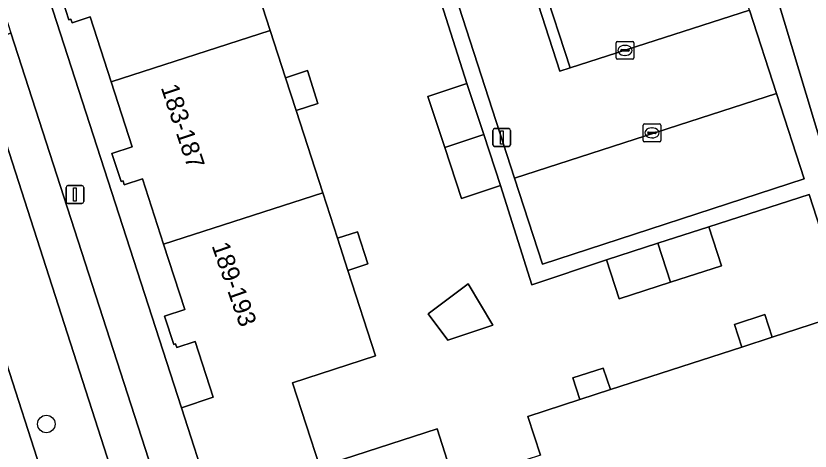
# Model space of a CAD drawing. Extents: x 159371 to 159986, y 382987 to 383597.
# Drawn here: x 159505.97 to 159550.53, y 383040.59 to 383065.02 of the extents above; entities that cross this region are included whole.
import ezdxf

# ---------------------------------------------------------------- set-up
doc = ezdxf.new("R2010")
doc.units = 0
for name, color, linetype in [('IMGEO_Boom', 7, 'Continuous'), ('IMGEO_Erf', 7, 'Continuous'), ('IMGEO_Fietspad_open', 7, 'Continuous'), ('IMGEO_Groenvoorziening', 7, 'Continuous'), ('IMGEO_Kolk', 7, 'Continuous'), ('IMGEO_Lichtmast', 7, 'Continuous'), ('IMGEO_Muur', 7, 'Continuous'), ('IMGEO_Pand', 7, 'Continuous'), ('IMGEO_Pand_nummerreeks', 7, 'Continuous'), ('IMGEO_Parkeervlak_open', 7, 'Continuous'), ('IMGEO_Rijbaan_lokaal_open', 7, 'Continuous'), ('IMGEO_Voetpad_open', 7, 'Continuous')]:
    doc.layers.add(name, color=color, linetype=linetype)

msp = doc.modelspace()

# ---------------------------------------------------------------- linework, layer by layer
at = {"layer": 'IMGEO_Boom'}
msp.add_circle((159507.682, 383042.11), 0.489, dxfattribs=at)
at = {"layer": 'IMGEO_Erf'}
for points in [[(159590.076, 383081.989), (159589.756, 383082.472), (159584.535, 383080.817), (159583.508, 383080.491), (159581.119, 383079.733), (159581.591, 383078.278), (159548.258, 383067.467), (159552.839, 383052.245), (159554.73, 383049.152), (159594.612, 383075.126)], [(159531.349, 383049.982), (159532.738, 383047.665), (159530.204, 383046.821), (159529.093, 383048.294)]]:
    msp.add_lwpolyline(points, close=True, dxfattribs=at)
for points in [[(159551.523, 383051.759), (159550.477, 383054.997), (159544.852, 383053.181), (159545.561, 383050.993), (159542.692, 383050.064), (159539.824, 383049.134), (159539.114, 383051.321), (159534.921, 383049.93), (159533.162, 383055.495), (159530.977, 383054.774), (159530.033, 383057.637), (159529.089, 383060.5), (159531.273, 383061.22), (159527.278, 383073.835)], [(159518.756, 383068.777), (159520.239, 383064.195), (159521.097, 383061.545), (159522.324, 383061.942), (159522.921, 383060.1), (159521.694, 383059.702), (159523.189, 383055.084), (159524.013, 383052.538), (159525.129, 383052.899), (159525.712, 383051.095), (159524.597, 383050.734), (159526.147, 383045.944), (159521.484, 383044.429), (159523.019, 383039.702), (159529.6, 383041.839), (159530.588, 383038.795)], [(159535.4, 383040.357), (159534.692, 383042.535), (159537.609, 383043.482), (159537.215, 383044.697), (159538.927, 383045.253), (159539.322, 383044.039), (159546.693, 383046.432), (159546.283, 383047.695), (159547.99, 383048.249), (159548.4, 383046.987), (159553.469, 383048.633)]]:
    msp.add_lwpolyline(points, dxfattribs=at)
at = {"layer": 'IMGEO_Fietspad_open'}
msp.add_arc((159691.276, 383107.789), 197.962, 197.58879, 201.43204, dxfattribs=at)
at = {"layer": 'IMGEO_Groenvoorziening'}
msp.add_lwpolyline([(159505.691, 383064.068), (159504.66, 383063.593), (159505.38, 383061.288), (159504.908, 383059.446), (159515.199, 383027.456), (159517.392, 383027.837)], close=True, dxfattribs=at)
for points in [[(159510.486, 383031.236), (159512.634, 383027.01), (159515.199, 383027.456), (159504.908, 383059.446), (159505.38, 383061.288), (159504.66, 383063.593), (159505.691, 383064.068)], [(159502.496, 383054.651), (159508.715, 383035.357)]]:
    msp.add_lwpolyline(points, dxfattribs=at)
at = {"layer": 'IMGEO_Kolk'}
for p, q in [((159539.642, 383062.653), (159539.642, 383063.505)), ((159539.717, 383063.579), (159540.569, 383063.579)), ((159540.643, 383063.505), (159540.643, 383062.653)), ((159539.901, 383063.073), (159539.901, 383063.085)), ((159540.339, 383063.036), (159539.941, 383063.036)), ((159539.944, 383063.122), (159540.342, 383063.122)), ((159540.13, 383063.359), (159540.155, 383063.359)), ((159540.385, 383063.085), (159540.385, 383063.073)), ((159540.569, 383062.579), (159539.717, 383062.579)), ((159540.153, 383062.799), (159540.128, 383062.799)), ((159541.155, 383058.025), (159541.155, 383058.877)), ((159541.23, 383058.951), (159542.082, 383058.951)), ((159541.643, 383058.731), (159541.668, 383058.731)), ((159542.156, 383058.877), (159542.156, 383058.025)), ((159541.414, 383058.445), (159541.414, 383058.457)), ((159541.852, 383058.408), (159541.454, 383058.408)), ((159541.457, 383058.494), (159541.855, 383058.494)), ((159541.666, 383058.171), (159541.641, 383058.171)), ((159541.898, 383058.457), (159541.898, 383058.445)), ((159542.082, 383057.951), (159541.23, 383057.951))]:
    msp.add_line(p, q, dxfattribs=at)
for points in [[(159539.642, 383062.653), (159539.642, 383063.505)], [(159539.717, 383063.579), (159540.569, 383063.579)], [(159540.643, 383063.505), (159540.643, 383062.653)], [(159540.569, 383062.579), (159539.717, 383062.579)], [(159541.155, 383058.025), (159541.155, 383058.877)], [(159541.23, 383058.951), (159542.082, 383058.951)], [(159542.156, 383058.877), (159542.156, 383058.025)], [(159542.082, 383057.951), (159541.23, 383057.951)]]:
    msp.add_lwpolyline(points, dxfattribs=at)
for centre, radius, start, end in [((159539.719, 383063.503), 0.0765, 91.552, 178.448), ((159539.719, 383063.503), 0.0765, 91.552, 178.448), ((159540.567, 383063.503), 0.0765, 1.552, 88.448), ((159540.567, 383063.503), 0.0765, 1.552, 88.448), ((159539.941, 383063.082), 0.0403, 85.8775, 175.7526), ((159539.938, 383063.072), 0.0366, 178.938, 274.7102), ((159540.342, 383063.079), 0.043, 264.8664, 352.4533), ((159540.346, 383063.084), 0.0386, 1.7309, 96.639), ((159539.719, 383062.655), 0.0765, 181.552, 268.448), ((159539.719, 383062.655), 0.0765, 181.552, 268.448), ((159540.567, 383062.655), 0.0765, 271.552, 358.448), ((159540.567, 383062.655), 0.0765, 271.552, 358.448), ((159541.232, 383058.875), 0.0765, 91.552, 178.448), ((159541.232, 383058.875), 0.0765, 91.552, 178.448), ((159542.08, 383058.875), 0.0765, 1.552, 88.448), ((159542.08, 383058.875), 0.0765, 1.552, 88.448), ((159541.454, 383058.454), 0.0403, 85.8775, 175.7526), ((159541.451, 383058.444), 0.0366, 178.938, 274.7102), ((159541.855, 383058.451), 0.043, 264.8664, 352.4533), ((159541.859, 383058.456), 0.0386, 1.7309, 96.639), ((159541.232, 383058.027), 0.0765, 181.552, 268.448), ((159541.232, 383058.027), 0.0765, 181.552, 268.448), ((159542.08, 383058.027), 0.0765, 271.552, 358.448), ((159542.08, 383058.027), 0.0765, 271.552, 358.448)]:
    msp.add_arc(centre, radius, start, end, dxfattribs=at)
for centre, major_axis, ratio, start_param, end_param in [((159540.129, 383063.079), (-0.387, 0.002), 0.722429, 4.712389, 7.853982), ((159540.154, 383063.079), (-0.39, 0.002), 0.717154, 1.570796, 4.712389), ((159541.642, 383058.451), (-0.387, 0.002), 0.722429, 4.712389, 7.853982), ((159541.667, 383058.451), (-0.39, 0.002), 0.717154, 1.570796, 4.712389)]:
    msp.add_ellipse(centre, major_axis=major_axis, ratio=ratio, start_param=start_param, end_param=end_param, dxfattribs=at)
at = {"layer": 'IMGEO_Lichtmast'}
for p, q in [((159532.731, 383057.787), (159532.731, 383058.587)), ((159532.731, 383058.587), (159532.731, 383057.787)), ((159532.831, 383058.687), (159533.621, 383058.687)), ((159533.621, 383058.687), (159532.831, 383058.687)), ((159533.721, 383058.587), (159533.721, 383057.787)), ((159533.721, 383057.787), (159533.721, 383058.587)), ((159533.621, 383057.687), (159532.831, 383057.687)), ((159532.831, 383057.687), (159533.621, 383057.687)), ((159508.886, 383055.491), (159509.676, 383055.491)), ((159509.676, 383055.491), (159508.886, 383055.491)), ((159508.786, 383054.591), (159508.786, 383055.391)), ((159508.786, 383055.391), (159508.786, 383054.591)), ((159509.776, 383055.391), (159509.776, 383054.591)), ((159509.776, 383054.591), (159509.776, 383055.391)), ((159509.676, 383054.491), (159508.886, 383054.491)), ((159508.886, 383054.491), (159509.676, 383054.491))]:
    msp.add_line(p, q, dxfattribs=at)
for points in [[(159533.151, 383058.562), (159533.301, 383058.562), (159533.301, 383057.812), (159533.151, 383057.812), (159533.151, 383058.562)], [(159509.206, 383055.366), (159509.356, 383055.366), (159509.356, 383054.616), (159509.206, 383054.616), (159509.206, 383055.366)]]:
    msp.add_lwpolyline(points, dxfattribs=at)
for centre, start, end in [((159532.831, 383058.587), 90, 180), ((159532.831, 383058.587), 90, 180), ((159533.621, 383058.587), 0, 90), ((159533.621, 383058.587), 360, 90), ((159532.831, 383057.787), 180, 270), ((159532.831, 383057.787), 180, 270), ((159533.621, 383057.787), 270, 0), ((159533.621, 383057.787), 270, 0), ((159508.886, 383055.391), 90, 180), ((159508.886, 383055.391), 90, 180), ((159509.676, 383055.391), 0, 90), ((159509.676, 383055.391), 360, 90), ((159508.886, 383054.591), 180, 270), ((159508.886, 383054.591), 180, 270), ((159509.676, 383054.591), 270, 0), ((159509.676, 383054.591), 270, 0)]:
    msp.add_arc(centre, 0.1, start, end, dxfattribs=at)
at = {"layer": 'IMGEO_Muur'}
for points in [[(159527.278, 383073.835), (159531.273, 383061.22)], [(159539.114, 383051.321), (159534.921, 383049.93), (159533.162, 383055.495)], [(159544.852, 383053.181), (159550.477, 383054.997)]]:
    msp.add_lwpolyline(points, dxfattribs=at)
at = {"layer": 'IMGEO_Pand'}
for points in [[(159518.756, 383068.777), (159518.086, 383070.848), (159517.273, 383073.361), (159508.363, 383070.484), (159509.565, 383066.759), (159508.431, 383066.382), (159508.949, 383064.802), (159509.054, 383064.837), (159509.123, 383064.628), (159510.145, 383064.963), (159511.322, 383061.317), (159520.239, 383064.195)], [(159521.694, 383059.702), (159521.097, 383061.545), (159520.239, 383064.195), (159511.322, 383061.317), (159512.498, 383057.672), (159511.364, 383057.295), (159511.882, 383055.715), (159511.987, 383055.75), (159512.056, 383055.541), (159513.078, 383055.876), (159514.262, 383052.204), (159523.189, 383055.084)], [(159521.097, 383061.545), (159521.694, 383059.702), (159522.921, 383060.1), (159522.324, 383061.942)], [(159530.033, 383057.637), (159532.218, 383058.358), (159531.273, 383061.22), (159529.089, 383060.5)], [(159530.033, 383057.637), (159530.977, 383054.774), (159533.162, 383055.495), (159532.218, 383058.358)], [(159521.484, 383044.429), (159526.147, 383045.944), (159524.597, 383050.734), (159524.013, 383052.538), (159523.189, 383055.084), (159514.262, 383052.204), (159515.447, 383048.532), (159514.313, 383048.155), (159514.831, 383046.575), (159514.936, 383046.61), (159515.005, 383046.401), (159516.028, 383046.736), (159517.034, 383043.617), (159515.265, 383043.021), (159518.438, 383033.149), (159522.589, 383034.496), (159524.454, 383035.101), (159523.976, 383036.575), (159523.019, 383039.702)], [(159542.692, 383050.064), (159545.561, 383050.993), (159544.852, 383053.181), (159541.983, 383052.251)], [(159524.013, 383052.538), (159524.597, 383050.734), (159525.712, 383051.095), (159525.129, 383052.899)], [(159542.692, 383050.064), (159541.983, 383052.251), (159539.114, 383051.321), (159539.824, 383049.134)], [(159529.093, 383048.294), (159530.204, 383046.821), (159532.738, 383047.665), (159531.349, 383049.982)], [(159556.336, 383044.392), (159554.984, 383043.971), (159553.469, 383048.633), (159548.4, 383046.987), (159546.693, 383046.432), (159539.322, 383044.039), (159537.609, 383043.482), (159534.692, 383042.535), (159535.4, 383040.357), (159530.588, 383038.795), (159529.6, 383041.839), (159523.019, 383039.702), (159523.976, 383036.575), (159526.049, 383037.247), (159526.758, 383035.059), (159525.407, 383034.621), (159526.629, 383030.733), (159557.552, 383040.764)], [(159546.693, 383046.432), (159548.4, 383046.987), (159547.99, 383048.249), (159546.283, 383047.695)], [(159537.609, 383043.482), (159539.322, 383044.039), (159538.927, 383045.253), (159537.215, 383044.697)]]:
    msp.add_lwpolyline(points, close=True, dxfattribs=at)
at = {"layer": 'IMGEO_Parkeervlak_open'}
for points in [[(159537.072, 383062.097), (159547.119, 383065.338), (159545.563, 383070.117), (159536.383, 383067.146), (159535.513, 383066.876)], [(159535.508, 383051.083), (159550.201, 383055.871), (159548.642, 383060.661), (159533.947, 383055.907)]]:
    msp.add_lwpolyline(points, close=True, dxfattribs=at)
at = {"layer": 'IMGEO_Rijbaan_lokaal_open'}
msp.add_lwpolyline([(159522.735, 383090.553), (159533.947, 383055.907), (159548.642, 383060.661), (159547.119, 383065.338), (159537.072, 383062.097), (159536.492, 383061.91), (159526.812, 383091.837)], close=True, dxfattribs=at)
at = {"layer": 'IMGEO_Voetpad_open'}
for points in [[(159502.13, 383068.926), (159503.942, 383069.485), (159505.691, 383064.068), (159517.392, 383027.837), (159519.89, 383028.504), (159519.135, 383030.973), (159523.829, 383032.582), (159524.666, 383030.142), (159526.629, 383030.733), (159525.407, 383034.621), (159526.758, 383035.059), (159526.049, 383037.247), (159523.976, 383036.575), (159524.454, 383035.101), (159522.589, 383034.496), (159518.438, 383033.149), (159515.265, 383043.021), (159500, 383090.154), (159491.71, 383115.676)], [(159526.812, 383091.837), (159536.492, 383061.91), (159537.072, 383062.097), (159535.513, 383066.876)], [(159547.119, 383065.338), (159548.642, 383060.661), (159550.201, 383055.871), (159535.508, 383051.083), (159533.947, 383055.907), (159522.735, 383090.553)], [(159500, 383090.154), (159515.265, 383043.021), (159517.034, 383043.617), (159516.028, 383046.736), (159515.005, 383046.401), (159514.936, 383046.61), (159514.831, 383046.575), (159514.313, 383048.155), (159515.447, 383048.532), (159514.262, 383052.204), (159513.078, 383055.876), (159512.056, 383055.541), (159511.987, 383055.75), (159511.882, 383055.715), (159511.364, 383057.295), (159512.498, 383057.672), (159511.322, 383061.317), (159510.145, 383064.963), (159509.123, 383064.628), (159509.054, 383064.837), (159508.949, 383064.802), (159508.431, 383066.382)], [(159527.278, 383073.835), (159531.273, 383061.22), (159532.218, 383058.358), (159533.162, 383055.495), (159534.921, 383049.93), (159539.114, 383051.321), (159541.983, 383052.251), (159544.852, 383053.181), (159550.477, 383054.997), (159551.523, 383051.759), (159553.469, 383048.633), (159554.984, 383043.971), (159556.336, 383044.392), (159557.552, 383040.764), (159559.512, 383041.791), (159554.73, 383049.152), (159552.839, 383052.245), (159548.258, 383067.467)], [(159508.715, 383035.357), (159502.496, 383054.651)]]:
    msp.add_lwpolyline(points, dxfattribs=at)
msp.add_arc((159691.276, 383107.789), 197.962, 197.58879, 201.43204, dxfattribs=at)

# ---------------------------------------------------------------- texts
at = {"layer": 'IMGEO_Pand_nummerreeks'}
for s, rotation, p in [('183-187', 288.4376, (159514.094, 383061)), ('189-193', 289.2741, (159516.943, 383052.119))]:
    msp.add_text(s, height=1, rotation=rotation, dxfattribs=at).set_placement(p)

doc.saveas('drawing.dxf')
